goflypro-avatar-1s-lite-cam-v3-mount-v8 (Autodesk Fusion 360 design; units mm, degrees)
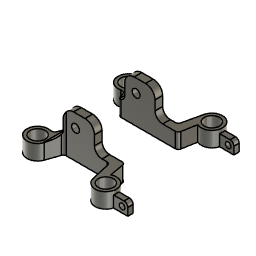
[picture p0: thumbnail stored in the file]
sketch "Skizze1" plane through (0, 0, 0) normal (0, 0, 1) x axis (1, 0, 0)
  line L1 (-7.919, 4) -> (-8.3877, 2.6607)
  line L2 (8.1804, 4) -> (8.4701, 2.3448)
  line L3 (8.7886, 0.5244) -> (8.4701, 2.3448)
  line L4 (-8.493, 2.3599) -> (-8.3877, 2.6607)
  line L5 (6, 3) -> (-6, 3)
  line L6 (8.0054, 5) -> (-7.569, 5)
  line L7 (-7.569, 5) -> (-7.919, 4)
  line L8 (8.0054, 5) -> (8.1804, 4)
  line L9 (-7.3537, -0.915) -> (-6, 3)
  line L10 (7.2688, -2.6169) -> (6, 3)
  line L11 (-6, 5) -> (-6, 3)
  line L12 (2, 5) -> (2, 3)
  circle C1 centre (-10, 0) radius 2
  circle C2 centre (10, -2) radius 2
  circle C3 centre (-10, 0) radius 2.8
  circle C4 centre (10, -2) radius 2.8
  point P10 (8.7886, 0.5244)
  point P11 (-8.493, 2.3599)
  point P15 (-7.3537, -0.915)
  point P17 (7.2688, -2.6169)
  point P18 (-6, 5)
  point P19 (2, 3)
  point P20 (2, 5)
  concentric C1 C3
  concentric C2 C4
  parallel L1 L4
  parallel L2 L3
  coincident C4 P10
  coincident C3 P11
  parallel L1 L7
  parallel L2 L8
  coincident C3 P15
  tangent C3 L9
  coincident C4 P17
  tangent C4 L10
  coincident L6 P18
  perpendicular L6 L11
  coincident L5 P19
  coincident L6 P20
  perpendicular L6 L12
  dimension "d1" diameter C1 = 4
  dimension "d2" diameter C2 = 4
  dimension "d3" diameter C3 = 5.6
  dimension "d4" diameter C4 = 5.6
extrude "Extrusion1" new body sketch "Skizze1" along normal blind 4 bodies "GoFlyPro - Avatar 1s lite cam-V3 mount - left"
extrude "Extrusion5" add sketch "Skizze1" profile of L5 L6 L11 L12 along normal blind 11
sketch "Skizze2" plane through (0, 5, 0) normal (0, -1, 0) x axis (1, 0, 0)
  line L1 (-7.3847, 0) -> (10, 0)
  line L2 (10, 0) -> (10, -6)
  line L3 (10, -6) -> (-7.3847, -6)
  line L4 (-7.3847, -6) -> (-7.3847, 0)
  line L5 (6.5, 0) -> (-6.5, 0)
  line L6 (-6.5, 8) -> (6.5, 8)
  line L7 (6.5, 8) -> (6.5, 0)
  line L8 (-6.5, 0) -> (-6.5, 8)
  line L9 (-7.919, 0) -> (8.1804, 0)
  line L10 (-7.919, 8) -> (-7.919, 0)
  line L11 (8.1804, 8) -> (-7.919, 8)
  line L12 (8.1804, 0) -> (8.1804, 8)
  line L13 (-7.569, 0) -> (8.0054, 0)
  line L14 (-6, 4) -> (-7.569, 4)
  line L15 (8.0054, 0) -> (8.0054, 4)
  line L16 (-7.569, 4) -> (-7.569, 0)
  line L17 (-6, 11) -> (-6, 4)
  line L18 (2, 11) -> (-6, 11)
  line L19 (2, 4) -> (2, 11)
  line L20 (8.0054, 4) -> (2, 4)
  circle C1 centre (-3, 7.5) radius 1.05
  dimension "d8" diameter C1 = 2.1
extrude "Extrusion2" cut sketch "Skizze2" profile of C1 along normal blind 2
fillet "Abrundung7" radius 1
fillet "Abrundung11" radius 0.8
fillet "Abrundung12" radius 0.8
work_plane "Arbeitsebene" AlongDistance 12
fillet "Abrundung13" radius 2.5
fillet "Abrundung14" radius 1.5
fillet "Abrundung15" radius 2
sketch "Skizze3" plane through (0, 0, 0) normal (0, 0, 1) x axis (1, 0, 0)
  line L1 (12.5, -2.7) -> (16.5, -2.7)
  line L2 (12.5, -1.3) -> (12.5, -2.7)
  line L3 (16.5, -1.3) -> (12.5, -1.3)
  line L4 (16.5, -2.7) -> (16.5, -1.3)
  horizontal L1
  vertical L2
  horizontal L3
  vertical L4
extrude "Extrusion6" add sketch "Skizze3" along normal blind 3
sketch "Skizze4" plane through (0, -2.7, 0) normal (0, -1, 0) x axis (1, 0, 0)
  line L1 (12.7111, 0) -> (12.7111, 3)
  line L2 (16.5, 0) -> (12.7111, 0)
  line L3 (16.5, 3) -> (16.5, 0)
  line L4 (12.7111, 3) -> (16.5, 3)
  circle C1 centre (15, 1.5) radius 0.75
  dimension "d62" diameter C1 = 1.5
extrude "Extrusion7" cut sketch "Skizze4" profile of C1 against normal blind 2
fillet "Abrundung16" radius 1
mirror "Spiegeln" mirrorStitchTolerance 0.1 bodies "GoFlyPro - Avatar 1s lite cam-V3 mount - right"
named bodies: "GoFlyPro - Avatar 1s lite cam-V3 mount - left", "GoFlyPro - Avatar 1s lite cam-V3 mount - right"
